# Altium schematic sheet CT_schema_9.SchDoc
size 274 x 160 mm
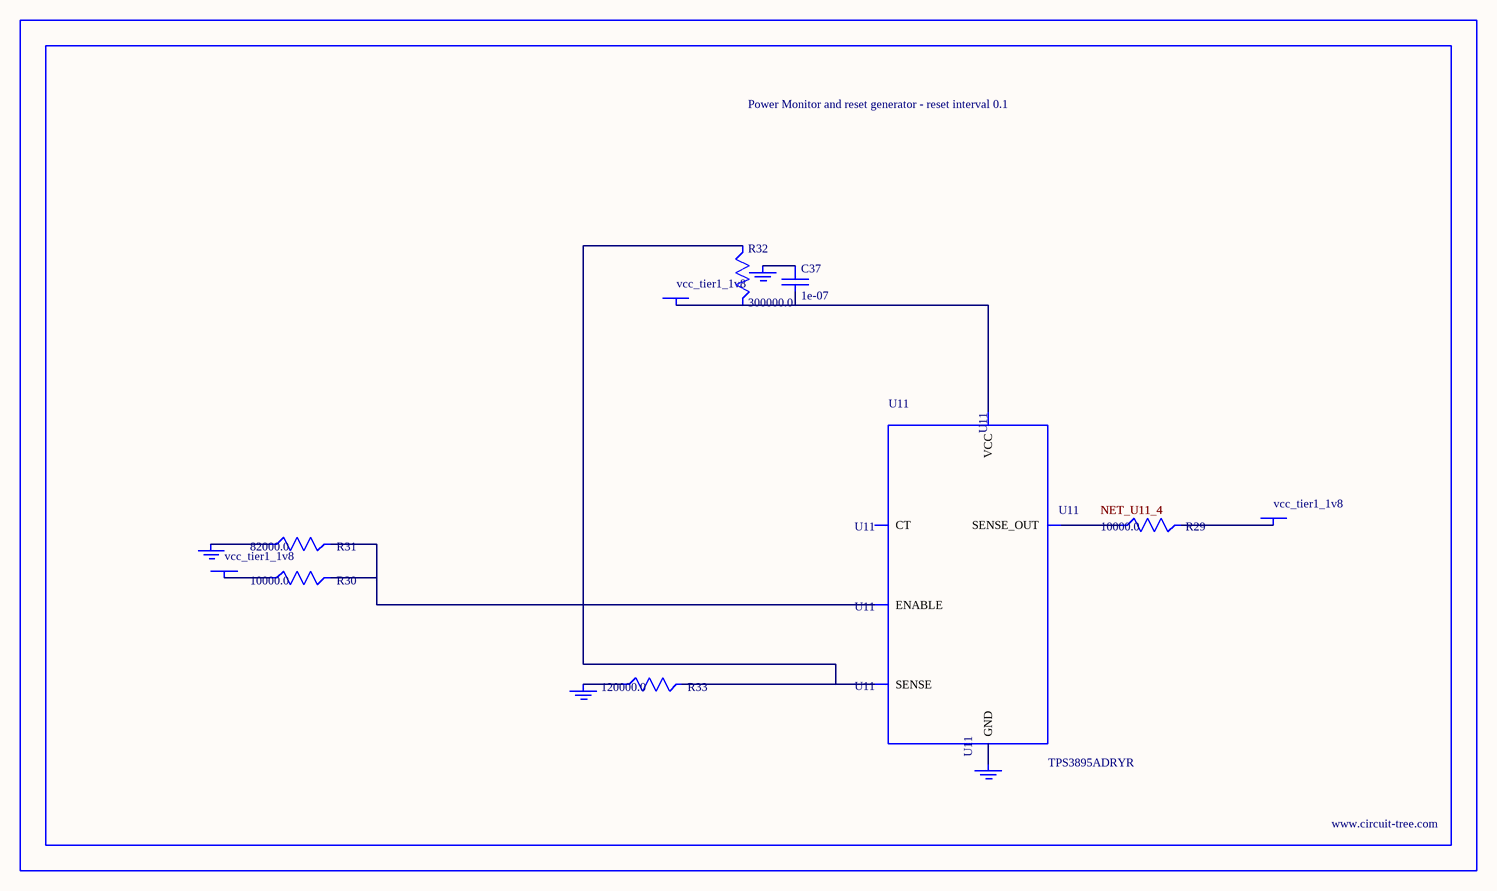
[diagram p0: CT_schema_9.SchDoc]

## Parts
BORDER8  (no value)
C37  1e-07  [C0402]
GND_INSTANCE_8_0  (no value)
GND_INSTANCE_8_1  (no value)
GND_INSTANCE_8_2  (no value)
GND_INSTANCE_8_3  (no value)
POWER_INSTANCE_8_0  vcc_tier1_1v8
POWER_INSTANCE_8_1  vcc_tier1_1v8
POWER_INSTANCE_8_2  vcc_tier1_1v8
R29  10000.0  [R0603]
R30  10000.0  [R0603]
R31  82000.0  [R0603]
R32  300000.0  [R0603]
R33  120000.0  [R0603]
U11  TPS3895ADRYR  [SON-6]

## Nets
NetC37_1: C37.1 GND_INSTANCE_8_2.0(GND)
NetC37_2: C37.2 POWER_INSTANCE_8_2.0(PWR) R32.2 U11.6(VCC)
NetGND_INSTANCE_8_0_0: GND_INSTANCE_8_0.0(GND) R31.1
NetGND_INSTANCE_8_1_0: GND_INSTANCE_8_1.0(GND) R33.1
NetGND_INSTANCE_8_3_0: GND_INSTANCE_8_3.0(GND) U11.2(GND)
NetPOWER_INSTANCE_8_0_0: POWER_INSTANCE_8_0.0(PWR) R30.1
NetPOWER_INSTANCE_8_1_0: POWER_INSTANCE_8_1.0(PWR) R29.2
NetR29_1: R29.1 U11.4(SENSE_OUT)
NetR30_2: R30.2 R31.2 U11.1(ENABLE)
NetR32_1: R32.1 R33.2 U11.3(SENSE)

Not connected (* = marked no-connect by the designer): U11 5(CT)

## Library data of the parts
BORDER8 = BORDER_PAGE8
C37 = C0402C104K3RACTU
GND_INSTANCE_8_0-GND_INSTANCE_8_3 = GND
POWER_INSTANCE_8_0-POWER_INSTANCE_8_2 = PWR
R29 R30 = RC0603JR-0710KL
R31 = RC0603JR-0782KL
R32 = RC0603JR-07300KL
R33 = RC0603JR-07120KL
